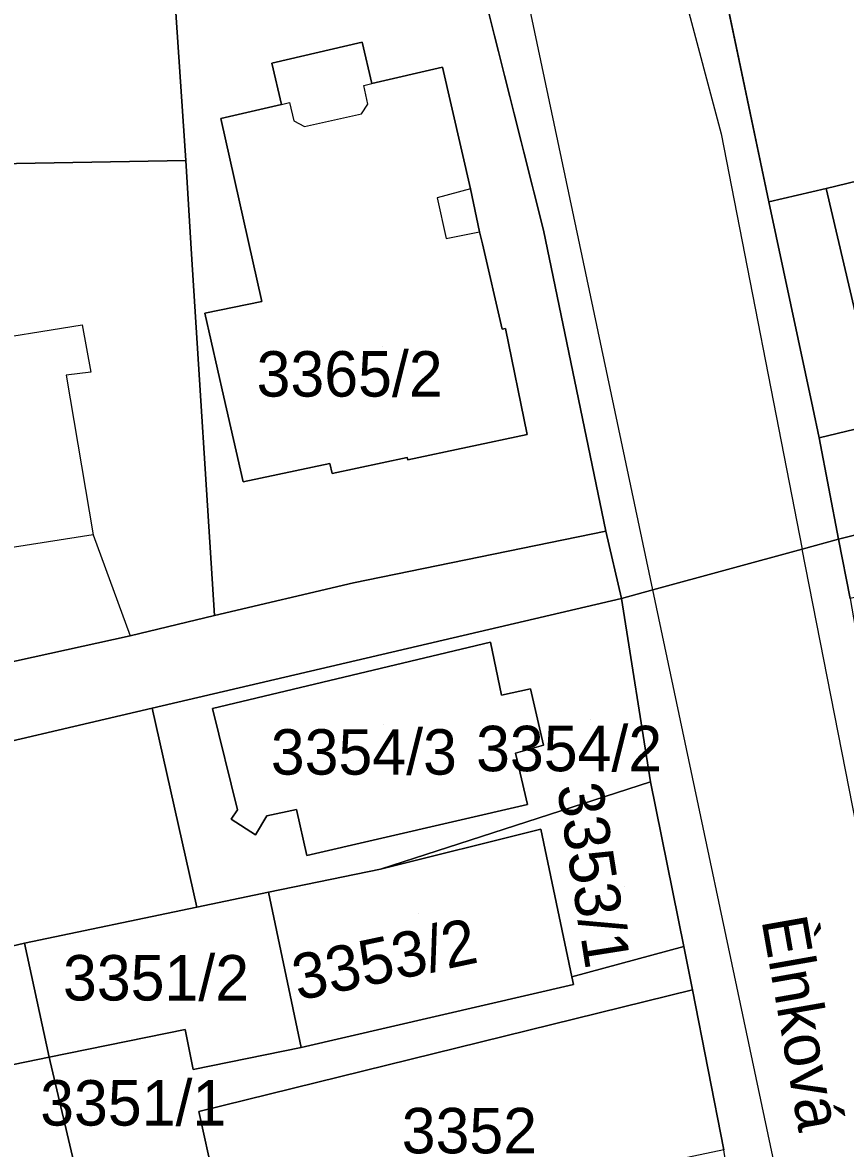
# Model space of a CAD drawing. Extents: x -262657 to -261595, y -1238015 to -1237156.
# Drawn here: x -261978.62 to -261942.44, y -1237697.83 to -1237648.33 of the extents above; entities that cross this region are included whole.
import ezdxf

# ---------------------------------------------------------------- set-up
doc = ezdxf.new("R2010")
doc.units = 0
for name, color, linetype in [('body_kn', 7, 'Continuous'), ('kladpar_druhypozemkov', 7, 'Continuous'), ('kladpar_hranice', 7, 'Continuous'), ('kladpar_parcelnecisla', 7, 'Continuous'), ('kladpar_plochy', 7, 'Continuous'), ('popisy', 7, 'Continuous'), ('zappar_hrandruhpozemk', 7, 'Continuous')]:
    doc.layers.add(name, color=color, linetype=linetype)

msp = doc.modelspace()

# ---------------------------------------------------------------- linework, layer by layer
at = {"layer": 'body_kn'}
for p, q in [((-261963.68, -1237649.19), (-261963.68, -1237649.19)), ((-261967.65, -1237650.12), (-261967.65, -1237650.12)), ((-261960.16, -1237650.3), (-261960.16, -1237650.3)), ((-261963.61, -1237651.1), (-261963.61, -1237651.1)), ((-261963.26, -1237651.01), (-261963.26, -1237651.01)), ((-261967.23, -1237651.94), (-261967.23, -1237651.94)), ((-261967.23, -1237651.94), (-261967.23, -1237651.94)), ((-261966.88, -1237651.85), (-261966.88, -1237651.85)), ((-261963.43, -1237651.92), (-261963.43, -1237651.92)), ((-261969.9, -1237652.55), (-261969.9, -1237652.55)), ((-261969.9, -1237652.55), (-261969.9, -1237652.55)), ((-261966.69, -1237652.65), (-261966.69, -1237652.65)), ((-261963.72, -1237652.34), (-261963.72, -1237652.34)), ((-261966.22, -1237652.91), (-261966.22, -1237652.91)), ((-261947.91, -1237653.22), (-261947.91, -1237653.22)), ((-261971.44, -1237654.4), (-261971.44, -1237654.4)), ((-261971.44, -1237654.4), (-261971.44, -1237654.4)), ((-261958.93, -1237655.64), (-261958.93, -1237655.64)), ((-261958.93, -1237655.64), (-261958.93, -1237655.64)), ((-261943.29, -1237655.63), (-261943.29, -1237655.63)), ((-261943.29, -1237655.63), (-261943.29, -1237655.63)), ((-261960.39, -1237656.04), (-261960.39, -1237656.04)), ((-261945.81, -1237656.22), (-261945.81, -1237656.22)), ((-261945.81, -1237656.22), (-261945.81, -1237656.22)), ((-261958.52, -1237657.53), (-261958.52, -1237657.53)), ((-261955.72, -1237657.46), (-261955.72, -1237657.46)), ((-261959.99, -1237657.82), (-261959.99, -1237657.82)), ((-261958.4, -1237658.06), (-261958.4, -1237658.06)), ((-261971.19, -1237658.51), (-261971.19, -1237658.51)), ((-261968.09, -1237660.59), (-261968.09, -1237660.59)), ((-261970.6, -1237661.11), (-261970.6, -1237661.11)), ((-261976, -1237661.63), (-261976, -1237661.63)), ((-261957.53, -1237661.82), (-261957.53, -1237661.82)), ((-261957.39, -1237661.79), (-261957.39, -1237661.79)), ((-261975.61, -1237663.7), (-261975.61, -1237663.7)), ((-261976.7, -1237663.84), (-261976.7, -1237663.84)), ((-261969.76, -1237664.81), (-261969.76, -1237664.81)), ((-261943.87, -1237665.27), (-261943.87, -1237665.27)), ((-261956.43, -1237666.45), (-261956.43, -1237666.45)), ((-261943.59, -1237666.59), (-261943.59, -1237666.59)), ((-261961.7, -1237667.45), (-261961.7, -1237667.45)), ((-261961.68, -1237667.56), (-261961.68, -1237667.56)), ((-261965.11, -1237667.72), (-261965.11, -1237667.72)), ((-261968.92, -1237668.53), (-261968.92, -1237668.53)), ((-261965.01, -1237668.16), (-261965.01, -1237668.16)), ((-261975.51, -1237670.85), (-261975.51, -1237670.85)), ((-261952.97, -1237670.7), (-261952.97, -1237670.7)), ((-261952.97, -1237670.7), (-261952.97, -1237670.7)), ((-261942.75, -1237671.05), (-261942.75, -1237671.05)), ((-261942.75, -1237671.05), (-261942.75, -1237671.05)), ((-261944.34, -1237671.48), (-261944.34, -1237671.48)), ((-261964.06, -1237672.97), (-261964.06, -1237672.97)), ((-261950.91, -1237673.28), (-261950.91, -1237673.28)), ((-261950.91, -1237673.28), (-261950.91, -1237673.28)), ((-261952.29, -1237673.66), (-261952.29, -1237673.66)), ((-261952.29, -1237673.66), (-261952.29, -1237673.66)), ((-261970.17, -1237674.4), (-261970.17, -1237674.4)), ((-261973.88, -1237675.29), (-261973.88, -1237675.29)), ((-261958.05, -1237675.58), (-261958.05, -1237675.58)), ((-261957.56, -1237677.91), (-261957.56, -1237677.91)), ((-261956.28, -1237677.62), (-261956.28, -1237677.62)), ((-261972.91, -1237678.48), (-261972.91, -1237678.48)), ((-261970.26, -1237678.49), (-261970.26, -1237678.49)), ((-261970.26, -1237678.49), (-261970.26, -1237678.49)), ((-261956.95, -1237680.45), (-261956.95, -1237680.45)), ((-261955.71, -1237680.1), (-261955.71, -1237680.1)), ((-261951.01, -1237681.71), (-261951.01, -1237681.71)), ((-261969.17, -1237682.94), (-261969.17, -1237682.94)), ((-261966.57, -1237682.93), (-261966.57, -1237682.93)), ((-261956.42, -1237682.71), (-261956.42, -1237682.71)), ((-261969.44, -1237683.36), (-261969.44, -1237683.36)), ((-261967.88, -1237683.21), (-261967.88, -1237683.21)), ((-261955.83, -1237683.79), (-261955.83, -1237683.79)), ((-261968.38, -1237684.05), (-261968.38, -1237684.05)), ((-261966.12, -1237684.96), (-261966.12, -1237684.96)), ((-261962.88, -1237685.55), (-261962.88, -1237685.55)), ((-261962.88, -1237685.55), (-261962.88, -1237685.55)), ((-261967.8, -1237686.57), (-261967.8, -1237686.57)), ((-261970.95, -1237687.23), (-261970.95, -1237687.23)), ((-261970.95, -1237687.23), (-261970.95, -1237687.23)), ((-261978.53, -1237688.81), (-261978.53, -1237688.81)), ((-261978.53, -1237688.81), (-261978.53, -1237688.81)), ((-261949.54, -1237688.95), (-261949.54, -1237688.95)), ((-261954.47, -1237690.29), (-261954.47, -1237690.29)), ((-261954.4, -1237690.63), (-261954.4, -1237690.63)), ((-261949.17, -1237690.86), (-261949.17, -1237690.86)), ((-261949.17, -1237690.86), (-261949.17, -1237690.86)), ((-261971.47, -1237692.6), (-261971.47, -1237692.6)), ((-261966.37, -1237693.4), (-261966.37, -1237693.4)), ((-261966.37, -1237693.4), (-261966.37, -1237693.4)), ((-261977.44, -1237693.82), (-261977.44, -1237693.82)), ((-261977.4, -1237694.01), (-261977.4, -1237694.01)), ((-261971.11, -1237694.36), (-261971.11, -1237694.36)), ((-261970.86, -1237696.21), (-261970.86, -1237696.21))]:
    msp.add_line(p, q, dxfattribs=at)
at = {"layer": 'kladpar_druhypozemkov'}
for p, q in [((-261962.79, -1237662.58), (-261962.79, -1237662.58)), ((-261953.64, -1237678.98), (-261953.64, -1237678.98)), ((-261962.76, -1237679.21), (-261962.76, -1237679.21)), ((-261952.17, -1237686.33), (-261952.17, -1237686.33)), ((-261961.21, -1237687.5), (-261961.21, -1237687.5)), ((-261971.5, -1237689.5), (-261971.5, -1237689.5)), ((-261973.35, -1237694.92), (-261973.35, -1237694.92)), ((-261958.57, -1237696.23), (-261958.57, -1237696.23))]:
    msp.add_line(p, q, dxfattribs=at)
at = {"layer": 'kladpar_hranice'}
for p, q in [((-261960.15, -1237639.82), (-261955.72, -1237657.46)), ((-261945.81, -1237656.22), (-261948.93, -1237641.32))]:
    msp.add_line(p, q, dxfattribs=at)
for points in [[(-261952.29, -1237673.66), (-261952.97, -1237670.7), (-261955.72, -1237657.46), (-261960.15, -1237639.82), (-261963.49, -1237628.42), (-261971.52, -1237603.32)], [(-261959.54, -1237608.49), (-261955.63, -1237620.56), (-261954.11, -1237624.97), (-261952.18, -1237630.99), (-261951.25, -1237633.64), (-261948.93, -1237641.32), (-261945.81, -1237656.22), (-261943.87, -1237665.27), (-261943.59, -1237666.59), (-261942.75, -1237671.05)], [(-261990.01, -1237630.12), (-261987.81, -1237630.03), (-261973.11, -1237629.45), (-261972.33, -1237641.16), (-261971.44, -1237654.4), (-261987.18, -1237654.68), (-261990.01, -1237630.12)], [(-261955.72, -1237657.46), (-261952.97, -1237670.7), (-261964.06, -1237672.97), (-261970.17, -1237674.4), (-261971.19, -1237658.51), (-261971.44, -1237654.4), (-261972.33, -1237641.16), (-261960.15, -1237639.82)], [(-261899.3, -1237645.4), (-261922.19, -1237650.58), (-261922.48, -1237650.65), (-261923.85, -1237650.98), (-261928.72, -1237652.14), (-261935.18, -1237653.67), (-261943.29, -1237655.63), (-261945.81, -1237656.22)], [(-261969.9, -1237652.55), (-261967.23, -1237651.94), (-261967.65, -1237650.12), (-261963.68, -1237649.19), (-261963.26, -1237651.01), (-261960.16, -1237650.3), (-261958.93, -1237655.64), (-261958.52, -1237657.53), (-261958.4, -1237658.06), (-261957.53, -1237661.82), (-261957.39, -1237661.79), (-261956.43, -1237666.45), (-261961.68, -1237667.56), (-261961.7, -1237667.45), (-261965.01, -1237668.16), (-261965.11, -1237667.72), (-261968.92, -1237668.53), (-261969.76, -1237664.81), (-261970.6, -1237661.11), (-261968.09, -1237660.59), (-261969.9, -1237652.55)], [(-261958.52, -1237657.53), (-261958.93, -1237655.64), (-261960.16, -1237650.3), (-261963.26, -1237651.01), (-261963.68, -1237649.19), (-261967.65, -1237650.12), (-261967.23, -1237651.94), (-261969.9, -1237652.55), (-261968.09, -1237660.59), (-261970.6, -1237661.11), (-261969.76, -1237664.81), (-261968.92, -1237668.53), (-261965.11, -1237667.72), (-261965.01, -1237668.16), (-261961.7, -1237667.45), (-261961.68, -1237667.56), (-261956.43, -1237666.45), (-261957.39, -1237661.79), (-261957.53, -1237661.82), (-261958.4, -1237658.06), (-261958.52, -1237657.53)], [(-261928.72, -1237652.14), (-261923.85, -1237650.98), (-261922.48, -1237650.65), (-261920.77, -1237661.1), (-261943.59, -1237666.59), (-261943.87, -1237665.27), (-261945.81, -1237656.22), (-261943.29, -1237655.63), (-261941.24, -1237664.38), (-261933.12, -1237662.48), (-261933.32, -1237661.65), (-261926.85, -1237660.13), (-261928.72, -1237652.14)], [(-261918.88, -1237665.11), (-261942.75, -1237671.05), (-261943.59, -1237666.59), (-261920.77, -1237661.1), (-261922.48, -1237650.65), (-261918.88, -1237665.11)], [(-261943.29, -1237655.63), (-261935.18, -1237653.67), (-261928.72, -1237652.14), (-261926.85, -1237660.13), (-261933.32, -1237661.65), (-261933.12, -1237662.48), (-261941.24, -1237664.38), (-261943.29, -1237655.63)], [(-261971.44, -1237654.4), (-261971.19, -1237658.51), (-261970.17, -1237674.4), (-261973.88, -1237675.29), (-261984.49, -1237677.62), (-261985.18, -1237673.03), (-261985.26, -1237672.38), (-261986.37, -1237663.28), (-261986.82, -1237659.64), (-261987.18, -1237654.68), (-261971.44, -1237654.4)], [(-261942.23, -1237673.66), (-261942.75, -1237671.05), (-261918.88, -1237665.11), (-261918.59, -1237665.04), (-261895.61, -1237659.32), (-261892.53, -1237658.72), (-261891.53, -1237661.6), (-261924.29, -1237669.63), (-261942.23, -1237673.66)], [(-261952.97, -1237670.7), (-261952.29, -1237673.66), (-261972.91, -1237678.48), (-261992.72, -1237683.11), (-261997.4, -1237684.28), (-262007.42, -1237686.45), (-262010.26, -1237687.05), (-262011.89, -1237684.04), (-262004.48, -1237682.3), (-261998.06, -1237680.82), (-261993.04, -1237679.61), (-261984.49, -1237677.62), (-261973.88, -1237675.29), (-261970.17, -1237674.4), (-261964.06, -1237672.97), (-261952.97, -1237670.7)], [(-261952.29, -1237673.66), (-261950.91, -1237673.28), (-261944.34, -1237671.48), (-261942.75, -1237671.05)], [(-261942.75, -1237671.05), (-261944.34, -1237671.48), (-261950.91, -1237673.28), (-261952.29, -1237673.66)], [(-261942.75, -1237671.05), (-261942.23, -1237673.66), (-261939.7, -1237688.39), (-261938.13, -1237694.52), (-261935.53, -1237705.41), (-261935.01, -1237706.9), (-261934.58, -1237708.05), (-261932.89, -1237712.5), (-261932.56, -1237713.37), (-261932.24, -1237714.5), (-261930.78, -1237719.6), (-261929.93, -1237722.81), (-261927.87, -1237729.47), (-261927.22, -1237731.79), (-261926.6, -1237733.88), (-261924.29, -1237741.53), (-261923.24, -1237745.09), (-261922.72, -1237746.19), (-261920.12, -1237752.32)], [(-261970.95, -1237687.23), (-261972.91, -1237678.48), (-261952.29, -1237673.66), (-261951.01, -1237681.71)], [(-261914.09, -1237816.76), (-261923.62, -1237819.21), (-261923.89, -1237818.34), (-261924, -1237817.96), (-261923.67, -1237817.87), (-261913.97, -1237813.57), (-261908.88, -1237811.31), (-261912.8, -1237801.81), (-261914.12, -1237798.61), (-261922.63, -1237778.24), (-261926.09, -1237769.65), (-261929.76, -1237759.16), (-261940.37, -1237728.85), (-261943.02, -1237721.29), (-261943.45, -1237719.94), (-261944.94, -1237715.14), (-261945.5, -1237713.33), (-261947.79, -1237697.89), (-261949.17, -1237690.86), (-261949.54, -1237688.95), (-261951.01, -1237681.71), (-261952.29, -1237673.66)], [(-261956.42, -1237682.71), (-261956.95, -1237680.45), (-261955.71, -1237680.1), (-261956.28, -1237677.62), (-261957.56, -1237677.91), (-261958.05, -1237675.58), (-261970.26, -1237678.49), (-261969.17, -1237682.94), (-261969.44, -1237683.36), (-261968.38, -1237684.05), (-261967.88, -1237683.21), (-261966.57, -1237682.93), (-261966.12, -1237684.96), (-261956.42, -1237682.71)], [(-261970.26, -1237678.49), (-261958.05, -1237675.58), (-261957.56, -1237677.91), (-261956.28, -1237677.62), (-261955.71, -1237680.1), (-261956.95, -1237680.45), (-261956.42, -1237682.71), (-261966.12, -1237684.96), (-261966.57, -1237682.93), (-261967.88, -1237683.21), (-261968.38, -1237684.05), (-261969.44, -1237683.36), (-261969.17, -1237682.94), (-261970.26, -1237678.49)], [(-261978.53, -1237688.81), (-261987.23, -1237690.86), (-261988.69, -1237691.19), (-261989.79, -1237691.43), (-261992.72, -1237683.11), (-261972.91, -1237678.48), (-261970.95, -1237687.23), (-261978.53, -1237688.81)], [(-261951.01, -1237681.71), (-261962.88, -1237685.55), (-261967.8, -1237686.57), (-261970.95, -1237687.23)], [(-261962.88, -1237685.55), (-261951.01, -1237681.71), (-261949.54, -1237688.95), (-261954.47, -1237690.29), (-261955.83, -1237683.79), (-261962.88, -1237685.55)], [(-261966.37, -1237693.4), (-261967.8, -1237686.57), (-261962.88, -1237685.55), (-261955.83, -1237683.79), (-261954.47, -1237690.29), (-261954.4, -1237690.63), (-261966.37, -1237693.4)], [(-261978.53, -1237688.81), (-261970.95, -1237687.23), (-261967.8, -1237686.57), (-261966.37, -1237693.4), (-261971.11, -1237694.36), (-261971.47, -1237692.6), (-261977.44, -1237693.82), (-261978.53, -1237688.81)], [(-261988.69, -1237691.19), (-261987.23, -1237690.86), (-261978.53, -1237688.81), (-261977.44, -1237693.82), (-261983.16, -1237694.99), (-261982.75, -1237696.85), (-261987.37, -1237697.78), (-261988.69, -1237691.19)], [(-261949.17, -1237690.86), (-261970.86, -1237696.21), (-261970.2, -1237699.2), (-261975.88, -1237700.45), (-261975.95, -1237700.18), (-261977.4, -1237694.01), (-261977.44, -1237693.82), (-261971.47, -1237692.6), (-261971.11, -1237694.36), (-261966.37, -1237693.4), (-261954.4, -1237690.63), (-261954.47, -1237690.29), (-261949.54, -1237688.95), (-261949.17, -1237690.86)], [(-261967.27, -1237702.11), (-261969.44, -1237702.61), (-261969.5, -1237702.34), (-261969.42, -1237702.32), (-261970.11, -1237699.18), (-261970.2, -1237699.2), (-261970.86, -1237696.21), (-261949.17, -1237690.86), (-261947.79, -1237697.89), (-261958.08, -1237700.07), (-261960.39, -1237700.58), (-261967.27, -1237702.11)], [(-262006.42, -1237695.36), (-261989.79, -1237691.43), (-261988.69, -1237691.19), (-261987.37, -1237697.78), (-261982.75, -1237696.85), (-261983.16, -1237694.99), (-261977.44, -1237693.82), (-261977.4, -1237694.01), (-261975.95, -1237700.18), (-261975.88, -1237700.45), (-261979.02, -1237701.14), (-261978.32, -1237704.28), (-261975.12, -1237703.57), (-261975.04, -1237703.9), (-261978.24, -1237704.59), (-262000.71, -1237709.77), (-262006.42, -1237695.36)]]:
    msp.add_lwpolyline(points, dxfattribs=at)
at = {"layer": 'kladpar_plochy'}
for p, q in [((-261960.15, -1237639.82), (-261955.72, -1237657.46)), ((-261971.44, -1237654.4), (-261972.33, -1237641.16)), ((-261945.81, -1237656.22), (-261948.93, -1237641.32)), ((-261963.68, -1237649.19), (-261967.65, -1237650.12)), ((-261963.26, -1237651.01), (-261963.68, -1237649.19)), ((-261967.65, -1237650.12), (-261967.23, -1237651.94)), ((-261960.16, -1237650.3), (-261963.26, -1237651.01)), ((-261958.93, -1237655.64), (-261960.16, -1237650.3)), ((-261967.23, -1237651.94), (-261969.9, -1237652.55)), ((-261969.9, -1237652.55), (-261968.09, -1237660.59)), ((-261935.18, -1237653.67), (-261943.29, -1237655.63)), ((-261971.19, -1237658.51), (-261971.44, -1237654.4)), ((-261958.52, -1237657.53), (-261958.93, -1237655.64)), ((-261943.29, -1237655.63), (-261945.81, -1237656.22)), ((-261958.4, -1237658.06), (-261958.52, -1237657.53)), ((-261955.72, -1237657.46), (-261952.97, -1237670.7)), ((-261957.53, -1237661.82), (-261958.4, -1237658.06)), ((-261970.17, -1237674.4), (-261971.19, -1237658.51)), ((-261968.09, -1237660.59), (-261970.6, -1237661.11)), ((-261970.6, -1237661.11), (-261969.76, -1237664.81)), ((-261957.39, -1237661.79), (-261957.53, -1237661.82)), ((-261956.43, -1237666.45), (-261957.39, -1237661.79)), ((-261969.76, -1237664.81), (-261968.92, -1237668.53)), ((-261961.68, -1237667.56), (-261956.43, -1237666.45)), ((-261965.01, -1237668.16), (-261961.7, -1237667.45)), ((-261961.7, -1237667.45), (-261961.68, -1237667.56)), ((-261968.92, -1237668.53), (-261965.11, -1237667.72)), ((-261965.11, -1237667.72), (-261965.01, -1237668.16)), ((-261952.97, -1237670.7), (-261964.06, -1237672.97)), ((-261964.06, -1237672.97), (-261970.17, -1237674.4)), ((-261972.91, -1237678.48), (-261952.29, -1237673.66)), ((-261952.29, -1237673.66), (-261951.01, -1237681.71)), ((-261958.05, -1237675.58), (-261970.26, -1237678.49)), ((-261957.56, -1237677.91), (-261958.05, -1237675.58)), ((-261956.28, -1237677.62), (-261957.56, -1237677.91)), ((-261955.71, -1237680.1), (-261956.28, -1237677.62)), ((-261970.95, -1237687.23), (-261972.91, -1237678.48)), ((-261970.26, -1237678.49), (-261969.17, -1237682.94)), ((-261956.95, -1237680.45), (-261955.71, -1237680.1)), ((-261956.42, -1237682.71), (-261956.95, -1237680.45)), ((-261951.01, -1237681.71), (-261962.88, -1237685.55)), ((-261969.17, -1237682.94), (-261969.44, -1237683.36)), ((-261967.88, -1237683.21), (-261966.57, -1237682.93)), ((-261966.57, -1237682.93), (-261966.12, -1237684.96)), ((-261966.12, -1237684.96), (-261956.42, -1237682.71)), ((-261969.44, -1237683.36), (-261968.38, -1237684.05)), ((-261968.38, -1237684.05), (-261967.88, -1237683.21)), ((-261962.88, -1237685.55), (-261967.8, -1237686.57)), ((-261967.8, -1237686.57), (-261970.95, -1237687.23))]:
    msp.add_line(p, q, dxfattribs=at)
for points in [[(-261959.54, -1237608.49), (-261955.63, -1237620.56), (-261954.11, -1237624.97), (-261952.18, -1237630.99), (-261951.25, -1237633.64), (-261948.93, -1237641.32), (-261945.81, -1237656.22), (-261943.87, -1237665.27), (-261943.59, -1237666.59), (-261942.75, -1237671.05), (-261944.34, -1237671.48), (-261950.91, -1237673.28), (-261952.29, -1237673.66), (-261952.97, -1237670.7), (-261955.72, -1237657.46), (-261960.15, -1237639.82), (-261963.49, -1237628.42), (-261971.52, -1237603.32)], [(-261940.37, -1237728.85), (-261943.02, -1237721.29), (-261943.45, -1237719.94), (-261944.94, -1237715.14), (-261945.5, -1237713.33), (-261947.79, -1237697.89), (-261949.17, -1237690.86), (-261949.54, -1237688.95), (-261951.01, -1237681.71), (-261952.29, -1237673.66), (-261950.91, -1237673.28), (-261944.34, -1237671.48), (-261942.75, -1237671.05), (-261942.23, -1237673.66)]]:
    msp.add_lwpolyline(points, dxfattribs=at)
for points in [[(-261990.01, -1237630.12), (-261987.81, -1237630.03), (-261973.11, -1237629.45), (-261972.33, -1237641.16), (-261971.44, -1237654.4), (-261987.18, -1237654.68)], [(-261969.9, -1237652.55), (-261967.23, -1237651.94), (-261967.65, -1237650.12), (-261963.68, -1237649.19), (-261963.26, -1237651.01), (-261960.16, -1237650.3), (-261958.93, -1237655.64), (-261958.52, -1237657.53), (-261958.4, -1237658.06), (-261957.53, -1237661.82), (-261957.39, -1237661.79), (-261956.43, -1237666.45), (-261961.68, -1237667.56), (-261961.7, -1237667.45), (-261965.01, -1237668.16), (-261965.11, -1237667.72), (-261968.92, -1237668.53), (-261969.76, -1237664.81), (-261970.6, -1237661.11), (-261968.09, -1237660.59)], [(-261928.72, -1237652.14), (-261923.85, -1237650.98), (-261922.48, -1237650.65), (-261920.77, -1237661.1), (-261943.59, -1237666.59), (-261943.87, -1237665.27), (-261945.81, -1237656.22), (-261943.29, -1237655.63), (-261941.24, -1237664.38), (-261933.12, -1237662.48), (-261933.32, -1237661.65), (-261926.85, -1237660.13)], [(-261918.88, -1237665.11), (-261942.75, -1237671.05), (-261943.59, -1237666.59), (-261920.77, -1237661.1), (-261922.48, -1237650.65)], [(-261943.29, -1237655.63), (-261935.18, -1237653.67), (-261928.72, -1237652.14), (-261926.85, -1237660.13), (-261933.32, -1237661.65), (-261933.12, -1237662.48), (-261941.24, -1237664.38)], [(-261971.44, -1237654.4), (-261971.19, -1237658.51), (-261970.17, -1237674.4), (-261973.88, -1237675.29), (-261984.49, -1237677.62), (-261985.18, -1237673.03), (-261985.26, -1237672.38), (-261986.37, -1237663.28), (-261986.82, -1237659.64), (-261987.18, -1237654.68)], [(-261942.23, -1237673.66), (-261942.75, -1237671.05), (-261918.88, -1237665.11), (-261918.59, -1237665.04), (-261895.61, -1237659.32), (-261892.53, -1237658.72), (-261891.53, -1237661.6), (-261924.29, -1237669.63)], [(-261952.97, -1237670.7), (-261952.29, -1237673.66), (-261972.91, -1237678.48), (-261992.72, -1237683.11), (-261997.4, -1237684.28), (-262007.42, -1237686.45), (-262010.26, -1237687.05), (-262011.89, -1237684.04), (-262004.48, -1237682.3), (-261998.06, -1237680.82), (-261993.04, -1237679.61), (-261984.49, -1237677.62), (-261973.88, -1237675.29), (-261970.17, -1237674.4), (-261964.06, -1237672.97)], [(-261970.26, -1237678.49), (-261958.05, -1237675.58), (-261957.56, -1237677.91), (-261956.28, -1237677.62), (-261955.71, -1237680.1), (-261956.95, -1237680.45), (-261956.42, -1237682.71), (-261966.12, -1237684.96), (-261966.57, -1237682.93), (-261967.88, -1237683.21), (-261968.38, -1237684.05), (-261969.44, -1237683.36), (-261969.17, -1237682.94)], [(-261978.53, -1237688.81), (-261987.23, -1237690.86), (-261988.69, -1237691.19), (-261989.79, -1237691.43), (-261992.72, -1237683.11), (-261972.91, -1237678.48), (-261970.95, -1237687.23)], [(-261962.88, -1237685.55), (-261951.01, -1237681.71), (-261949.54, -1237688.95), (-261954.47, -1237690.29), (-261955.83, -1237683.79)], [(-261966.37, -1237693.4), (-261967.8, -1237686.57), (-261962.88, -1237685.55), (-261955.83, -1237683.79), (-261954.47, -1237690.29), (-261954.4, -1237690.63)], [(-261978.53, -1237688.81), (-261970.95, -1237687.23), (-261967.8, -1237686.57), (-261966.37, -1237693.4), (-261971.11, -1237694.36), (-261971.47, -1237692.6), (-261977.44, -1237693.82)], [(-261988.69, -1237691.19), (-261987.23, -1237690.86), (-261978.53, -1237688.81), (-261977.44, -1237693.82), (-261983.16, -1237694.99), (-261982.75, -1237696.85), (-261987.37, -1237697.78)], [(-261949.17, -1237690.86), (-261970.86, -1237696.21), (-261970.2, -1237699.2), (-261975.88, -1237700.45), (-261975.95, -1237700.18), (-261977.4, -1237694.01), (-261977.44, -1237693.82), (-261971.47, -1237692.6), (-261971.11, -1237694.36), (-261966.37, -1237693.4), (-261954.4, -1237690.63), (-261954.47, -1237690.29), (-261949.54, -1237688.95)], [(-261967.27, -1237702.11), (-261969.44, -1237702.61), (-261969.5, -1237702.34), (-261969.42, -1237702.32), (-261970.11, -1237699.18), (-261970.2, -1237699.2), (-261970.86, -1237696.21), (-261949.17, -1237690.86), (-261947.79, -1237697.89), (-261958.08, -1237700.07), (-261960.39, -1237700.58)], [(-262006.42, -1237695.36), (-261989.79, -1237691.43), (-261988.69, -1237691.19), (-261987.37, -1237697.78), (-261982.75, -1237696.85), (-261983.16, -1237694.99), (-261977.44, -1237693.82), (-261977.4, -1237694.01), (-261975.95, -1237700.18), (-261975.88, -1237700.45), (-261979.02, -1237701.14), (-261978.32, -1237704.28), (-261975.12, -1237703.57), (-261975.04, -1237703.9), (-261978.24, -1237704.59), (-262000.71, -1237709.77)]]:
    msp.add_lwpolyline(points, close=True, dxfattribs=at)
at = {"layer": 'zappar_hrandruhpozemk'}
for p, q in [((-261952.08, -1237637.52), (-261947.91, -1237653.22)), ((-261950.91, -1237673.28), (-261957.8, -1237640.72)), ((-261966.22, -1237652.91), (-261963.72, -1237652.34)), ((-261947.91, -1237653.22), (-261944.34, -1237671.48)), ((-261958.93, -1237655.64), (-261960.39, -1237656.04)), ((-261960.39, -1237656.04), (-261959.99, -1237657.82)), ((-261959.99, -1237657.82), (-261958.52, -1237657.53)), ((-261975.51, -1237670.85), (-261985.26, -1237672.38)), ((-261975.51, -1237670.85), (-261973.88, -1237675.29)), ((-261938.03, -1237703.73), (-261944.34, -1237671.48)), ((-261943.1, -1237710.14), (-261950.91, -1237673.28))]:
    msp.add_line(p, q, dxfattribs=at)
for points in [[(-261963.72, -1237652.34), (-261963.43, -1237651.92), (-261963.61, -1237651.1), (-261963.26, -1237651.01)], [(-261967.23, -1237651.94), (-261966.88, -1237651.85), (-261966.69, -1237652.65), (-261966.22, -1237652.91)], [(-261981.54, -1237658.68), (-261980.92, -1237662.41), (-261976, -1237661.63), (-261975.61, -1237663.7), (-261976.7, -1237663.84), (-261975.51, -1237670.85)]]:
    msp.add_lwpolyline(points, dxfattribs=at)

# ---------------------------------------------------------------- texts
at = {"layer": 'kladpar_parcelnecisla'}
for s, p in [('3365/2', (-261968.327, -1237664.78)), ('3354/3', (-261967.702, -1237681.4)), ('3354/2', (-261958.677, -1237681.25)), ('3351/2', (-261976.837, -1237691.33)), ('3351/1', (-261977.841, -1237696.83)), ('3352', (-261961.947, -1237698.05))]:
    msp.add_text(s, height=2, dxfattribs=at).set_placement(p)
for s, rotation, p in [('3353/1', 279, (-261955.129, -1237681.913)), ('3353/2', 12, (-261966.505, -1237691.34))]:
    msp.add_text(s, height=2, rotation=rotation, dxfattribs=at).set_placement(p)
at = {"layer": 'popisy'}
msp.add_text('Èlnková', height=2, rotation=280, dxfattribs=at).set_placement((-261946.137, -1237687.792))

doc.saveas('drawing.dxf')
